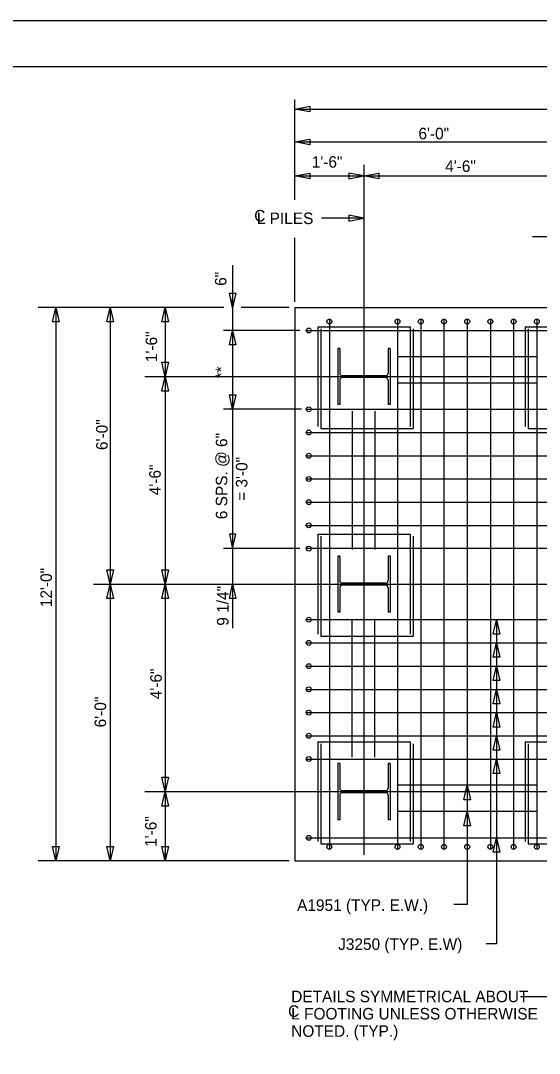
# Model space of a CAD drawing. Extents: x 1970675.2 to 1970711.3, y 796145.2 to 796167.2.
# Drawn here: x 1970688.23 to 1970693.86, y 796156.05 to 796167.25 of the extents above; entities that cross this region are included whole.
import ezdxf

# ---------------------------------------------------------------- set-up
doc = ezdxf.new("R2010")
doc.units = 0
for name, color, linetype in [('BR_AUTO DIMENSION', 7, 'Continuous'), ('BR_BORDER LINES', 7, 'Continuous'), ('BR_CENTER LINES', 7, 'Continuous'), ('BR_CONCRETE', 7, 'Continuous'), ('BR_REBAR', 7, 'Continuous'), ('BR_STRUCTURAL STEEL', 7, 'Continuous'), ('BR_TEXT', 7, 'Continuous'), ('Level 31', 7, 'Continuous')]:
    doc.layers.add(name, color=color, linetype=linetype)

msp = doc.modelspace()

# ---------------------------------------------------------------- linework, layer by layer
at = {"layer": 'BR_AUTO DIMENSION'}
for p, q in [((1970691.208, 796165.302), (1970691.208, 796166.393)), ((1970691.208, 796166.288), (1970697.208, 796166.288)), ((1970691.208, 796165.931), (1970694.208, 796165.931)), ((1970691.208, 796165.563), (1970691.958, 796165.563)), ((1970691.958, 796165.563), (1970694.208, 796165.563)), ((1970691.958, 796165.105), (1970691.497, 796165.105)), ((1970691.208, 796164.197), (1970691.208, 796164.89)), ((1970694.208, 796164.904), (1970693.787, 796164.904)), ((1970690.534, 796164.597), (1970690.534, 796160.661)), ((1970690.534, 796164.137), (1970690.534, 796164.24)), ((1970690.439, 796164.137), (1970688.423, 796164.137)), ((1970688.615, 796164.137), (1970688.615, 796158.137)), ((1970689.204, 796164.137), (1970689.204, 796161.137)), ((1970689.802, 796164.137), (1970689.802, 796163.387)), ((1970691.148, 796164.137), (1970690.628, 796164.137)), ((1970691.264, 796163.887), (1970690.435, 796163.887)), ((1970689.802, 796163.387), (1970689.802, 796161.137)), ((1970691.282, 796163.033), (1970690.435, 796163.033)), ((1970691.261, 796161.522), (1970690.435, 796161.522)), ((1970689.204, 796161.137), (1970689.204, 796158.137)), ((1970689.802, 796161.137), (1970689.802, 796158.137)), ((1970693.397, 796160.751), (1970693.397, 796157.238)), ((1970693.079, 796158.956), (1970693.079, 796157.664)), ((1970689.802, 796158.762), (1970689.802, 796158.663)), ((1970689.802, 796158.137), (1970689.802, 796158.227)), ((1970691.148, 796158.137), (1970688.423, 796158.137)), ((1970693.079, 796157.664), (1970692.934, 796157.664)), ((1970693.397, 796157.238), (1970693.283, 796157.238)), ((1970694.208, 796156.663), (1970693.656, 796156.663))]:
    msp.add_line(p, q, dxfattribs=at)
for points in [[(1970691.37, 796166.257), (1970691.208, 796166.288), (1970691.37, 796166.319)], [(1970691.37, 796165.9), (1970691.208, 796165.931), (1970691.37, 796165.962)], [(1970691.37, 796165.532), (1970691.208, 796165.563), (1970691.37, 796165.594)], [(1970691.795, 796165.532), (1970691.958, 796165.563), (1970691.795, 796165.594)], [(1970692.12, 796165.532), (1970691.958, 796165.563), (1970692.12, 796165.594)], [(1970691.795, 796165.074), (1970691.958, 796165.105), (1970691.795, 796165.136)], [(1970690.57, 796164.293), (1970690.534, 796164.137), (1970690.498, 796164.293)], [(1970688.579, 796163.981), (1970688.615, 796164.137), (1970688.651, 796163.981)], [(1970689.168, 796163.981), (1970689.204, 796164.137), (1970689.24, 796163.981)], [(1970689.766, 796163.981), (1970689.802, 796164.137), (1970689.838, 796163.981)], [(1970690.498, 796163.731), (1970690.534, 796163.887), (1970690.57, 796163.731)], [(1970689.837, 796163.545), (1970689.801, 796163.389), (1970689.765, 796163.545)], [(1970689.766, 796163.231), (1970689.802, 796163.387), (1970689.838, 796163.231)], [(1970690.57, 796163.189), (1970690.534, 796163.033), (1970690.498, 796163.189)], [(1970690.498, 796161.678), (1970690.534, 796161.522), (1970690.57, 796161.678)], [(1970689.24, 796161.293), (1970689.204, 796161.137), (1970689.168, 796161.293)], [(1970689.838, 796161.293), (1970689.802, 796161.137), (1970689.766, 796161.293)], [(1970689.168, 796160.981), (1970689.204, 796161.137), (1970689.24, 796160.981)], [(1970689.766, 796160.981), (1970689.802, 796161.137), (1970689.838, 796160.981)], [(1970690.498, 796160.981), (1970690.534, 796161.137), (1970690.57, 796160.981)], [(1970693.361, 796160.595), (1970693.397, 796160.751), (1970693.433, 796160.595)], [(1970693.361, 796160.344), (1970693.397, 796160.5), (1970693.433, 796160.344)], [(1970693.361, 796160.092), (1970693.397, 796160.248), (1970693.433, 796160.092)], [(1970693.361, 796159.84), (1970693.397, 796159.996), (1970693.433, 796159.84)], [(1970693.361, 796159.588), (1970693.397, 796159.744), (1970693.433, 796159.588)], [(1970693.361, 796159.337), (1970693.397, 796159.493), (1970693.433, 796159.337)], [(1970693.361, 796159.085), (1970693.397, 796159.241), (1970693.433, 796159.085)], [(1970689.838, 796159.043), (1970689.802, 796158.887), (1970689.766, 796159.043)], [(1970689.766, 796158.731), (1970689.802, 796158.887), (1970689.838, 796158.731)], [(1970693.043, 796158.8), (1970693.079, 796158.956), (1970693.115, 796158.8)], [(1970693.043, 796158.515), (1970693.079, 796158.671), (1970693.115, 796158.515)], [(1970693.361, 796158.231), (1970693.397, 796158.387), (1970693.433, 796158.231)], [(1970688.651, 796158.293), (1970688.615, 796158.137), (1970688.579, 796158.293)], [(1970689.24, 796158.293), (1970689.204, 796158.137), (1970689.168, 796158.293)], [(1970689.838, 796158.293), (1970689.802, 796158.137), (1970689.766, 796158.293)]]:
    msp.add_lwpolyline(points, close=True, dxfattribs=at)
at = {"layer": 'BR_BORDER LINES'}
msp.add_line((1970710.736, 796166.746), (1970677.07, 796166.746), dxfattribs=at)
at = {"layer": 'BR_CENTER LINES'}
for p, q in [((1970691.958, 796165.684), (1970691.958, 796158.201)), ((1970689.58, 796163.387), (1970698.526, 796163.387)), ((1970689.025, 796161.137), (1970699.298, 796161.137)), ((1970689.58, 796158.887), (1970698.435, 796158.887))]:
    msp.add_line(p, q, dxfattribs=at)
at = {"layer": 'BR_CONCRETE'}
for p, q in [((1970691.208, 796164.137), (1970697.208, 796164.137)), ((1970691.208, 796164.137), (1970691.208, 796158.137)), ((1970691.208, 796158.137), (1970697.208, 796158.137))]:
    msp.add_line(p, q, dxfattribs=at)
at = {"layer": 'BR_REBAR'}
for p, q in [((1970691.458, 796163.928), (1970692.458, 796163.928)), ((1970691.458, 796163.928), (1970691.458, 796162.845)), ((1970691.49, 796163.906), (1970691.49, 796162.823)), ((1970691.583, 796164.012), (1970691.583, 796158.262)), ((1970692.322, 796164.012), (1970692.322, 796158.262)), ((1970692.458, 796163.928), (1970692.458, 796162.845)), ((1970692.49, 796163.906), (1970692.49, 796162.823)), ((1970692.574, 796164.012), (1970692.574, 796158.262)), ((1970692.826, 796164.012), (1970692.826, 796158.262)), ((1970693.078, 796164.012), (1970693.078, 796158.262)), ((1970693.329, 796164.012), (1970693.329, 796158.262)), ((1970693.581, 796164.012), (1970693.581, 796158.262)), ((1970693.708, 796163.928), (1970694.708, 796163.928)), ((1970693.708, 796163.928), (1970693.708, 796162.845)), ((1970693.74, 796163.906), (1970693.74, 796162.823)), ((1970693.833, 796164.012), (1970693.833, 796158.262)), ((1970693.833, 796164.012), (1970693.833, 796158.262)), ((1970691.333, 796163.887), (1970697.083, 796163.887)), ((1970693.833, 796163.602), (1970692.333, 796163.602)), ((1970693.833, 796163.317), (1970692.333, 796163.317)), ((1970691.333, 796163.033), (1970697.083, 796163.033)), ((1970691.829, 796163.012), (1970691.829, 796161.512)), ((1970692.076, 796163.012), (1970692.076, 796161.512)), ((1970691.49, 796162.823), (1970692.49, 796162.823)), ((1970693.74, 796162.823), (1970694.74, 796162.823)), ((1970691.333, 796162.781), (1970697.083, 796162.781)), ((1970691.333, 796162.529), (1970697.083, 796162.529)), ((1970691.333, 796162.277), (1970697.083, 796162.277)), ((1970691.333, 796162.026), (1970697.083, 796162.026)), ((1970691.333, 796161.774), (1970697.083, 796161.774)), ((1970691.458, 796161.678), (1970692.458, 796161.678)), ((1970691.458, 796161.678), (1970691.458, 796160.595)), ((1970692.458, 796161.678), (1970692.458, 796160.595)), ((1970691.49, 796161.656), (1970691.49, 796160.573)), ((1970692.49, 796161.656), (1970692.49, 796160.573)), ((1970697.083, 796161.522), (1970691.333, 796161.522)), ((1970692.416, 796161.137), (1970696, 796161.137)), ((1970697.083, 796160.751), (1970691.333, 796160.751)), ((1970691.829, 796159.262), (1970691.829, 796160.762)), ((1970692.076, 796159.262), (1970692.076, 796160.762)), ((1970691.49, 796160.573), (1970692.49, 796160.573)), ((1970691.333, 796160.5), (1970697.083, 796160.5)), ((1970691.333, 796160.248), (1970697.083, 796160.248)), ((1970691.333, 796159.996), (1970697.083, 796159.996)), ((1970691.333, 796159.744), (1970697.083, 796159.744)), ((1970691.333, 796159.493), (1970697.083, 796159.493)), ((1970691.458, 796159.428), (1970692.458, 796159.428)), ((1970691.458, 796159.428), (1970691.458, 796158.345)), ((1970692.458, 796159.428), (1970692.458, 796158.345)), ((1970693.708, 796159.428), (1970694.708, 796159.428)), ((1970693.708, 796159.428), (1970693.708, 796158.345)), ((1970691.49, 796159.406), (1970691.49, 796158.323)), ((1970692.49, 796159.406), (1970692.49, 796158.323)), ((1970693.74, 796159.406), (1970693.74, 796158.323)), ((1970691.333, 796159.241), (1970697.083, 796159.241)), ((1970693.833, 796158.956), (1970692.333, 796158.956)), ((1970693.833, 796158.671), (1970692.333, 796158.671)), ((1970691.333, 796158.387), (1970697.083, 796158.387)), ((1970691.49, 796158.323), (1970692.49, 796158.323)), ((1970693.74, 796158.323), (1970694.74, 796158.323))]:
    msp.add_line(p, q, dxfattribs=at)
for centre in [(1970691.359, 796163.887), (1970691.583, 796163.985), (1970692.322, 796163.985), (1970692.574, 796163.985), (1970692.826, 796163.985), (1970693.078, 796163.985), (1970693.329, 796163.985), (1970693.581, 796163.985), (1970693.833, 796163.985), (1970693.833, 796163.985), (1970691.359, 796163.033), (1970691.359, 796162.781), (1970691.359, 796162.529), (1970691.359, 796162.277), (1970691.359, 796162.026), (1970691.359, 796161.774), (1970691.359, 796161.522), (1970691.359, 796160.751), (1970691.359, 796160.5), (1970691.359, 796160.248), (1970691.359, 796159.996), (1970691.359, 796159.744), (1970691.359, 796159.493), (1970691.359, 796159.241), (1970691.359, 796158.387), (1970691.583, 796158.288), (1970692.322, 796158.288), (1970692.574, 796158.288), (1970692.826, 796158.288), (1970693.078, 796158.288), (1970693.329, 796158.288), (1970693.581, 796158.288), (1970693.833, 796158.288), (1970693.833, 796158.288)]:
    msp.add_circle(centre, 0.0265, dxfattribs=at)
at = {"layer": 'BR_STRUCTURAL STEEL'}
for p, q in [((1970691.675, 796163.691), (1970691.675, 796163.083)), ((1970691.695, 796163.691), (1970691.675, 796163.691)), ((1970691.695, 796163.691), (1970691.695, 796163.425)), ((1970692.22, 796163.691), (1970692.22, 796163.425)), ((1970692.241, 796163.691), (1970692.22, 796163.691)), ((1970692.241, 796163.691), (1970692.241, 796163.083)), ((1970691.695, 796163.348), (1970691.695, 796163.083)), ((1970692.192, 796163.397), (1970691.723, 796163.397)), ((1970692.192, 796163.376), (1970691.723, 796163.376)), ((1970692.22, 796163.348), (1970692.22, 796163.083)), ((1970691.695, 796163.083), (1970691.675, 796163.083)), ((1970692.241, 796163.083), (1970692.22, 796163.083)), ((1970691.675, 796161.441), (1970691.675, 796160.833)), ((1970691.695, 796161.441), (1970691.675, 796161.441)), ((1970691.695, 796161.441), (1970691.695, 796161.175)), ((1970692.22, 796161.441), (1970692.22, 796161.175)), ((1970692.241, 796161.441), (1970692.22, 796161.441)), ((1970692.241, 796161.441), (1970692.241, 796160.833)), ((1970692.192, 796161.147), (1970691.723, 796161.147)), ((1970692.192, 796161.126), (1970691.723, 796161.126)), ((1970691.695, 796161.098), (1970691.695, 796160.833)), ((1970692.22, 796161.098), (1970692.22, 796160.833)), ((1970691.695, 796160.833), (1970691.675, 796160.833)), ((1970692.241, 796160.833), (1970692.22, 796160.833)), ((1970691.675, 796159.191), (1970691.675, 796158.583)), ((1970691.695, 796159.191), (1970691.675, 796159.191)), ((1970691.695, 796159.191), (1970691.695, 796158.925)), ((1970692.22, 796159.191), (1970692.22, 796158.925)), ((1970692.241, 796159.191), (1970692.22, 796159.191)), ((1970692.241, 796159.191), (1970692.241, 796158.583)), ((1970692.192, 796158.897), (1970691.723, 796158.897)), ((1970692.192, 796158.876), (1970691.723, 796158.876)), ((1970691.695, 796158.848), (1970691.695, 796158.583)), ((1970692.22, 796158.848), (1970692.22, 796158.583)), ((1970691.695, 796158.583), (1970691.675, 796158.583)), ((1970692.241, 796158.583), (1970692.22, 796158.583))]:
    msp.add_line(p, q, dxfattribs=at)
for centre, start, end in [((1970691.723, 796163.425), 180, 270), ((1970691.723, 796163.348), 90, 180), ((1970692.192, 796163.425), 270, 360), ((1970692.192, 796163.348), 360, 90), ((1970691.723, 796161.175), 180, 270), ((1970691.723, 796161.098), 90, 180), ((1970692.192, 796161.175), 270, 360), ((1970692.192, 796161.098), 360, 90), ((1970691.723, 796158.925), 180, 270), ((1970691.723, 796158.848), 90, 180), ((1970692.192, 796158.925), 270, 360), ((1970692.192, 796158.848), 360, 90)]:
    msp.add_arc(centre, 0.0281, start, end, dxfattribs=at)
at = {"layer": 'Level 31'}
msp.add_lwpolyline([(1970675.236, 796145.246), (1970711.236, 796145.246), (1970711.236, 796167.246), (1970675.236, 796167.246)], close=True, dxfattribs=at)

# ---------------------------------------------------------------- texts
at = {"layer": 'BR_AUTO DIMENSION'}
for s, p in [('6\'-0"', (1970692.549, 796165.96)), ('C', (1970690.768, 796165.069)), ('C', (1970691.135, 796156.445))]:
    msp.add_text(s, height=0.125, dxfattribs=at).set_placement(p)
at = {"layer": 'BR_TEXT'}
for s, p in [('1\'-6"', (1970691.392, 796165.652)), ('4\'-6"', (1970692.839, 796165.606)), ('L PILES', (1970690.796, 796165.041)), ('A1951 (TYP. E.W.)', (1970691.233, 796157.594)), ('J3250 (TYP. E.W)', (1970691.678, 796157.171)), ('DETAILS SYMMETRICAL ABOUT ', (1970691.169, 796156.604)), ('L FOOTING UNLESS OTHERWISE', (1970691.169, 796156.417)), ('NOTED. (TYP.)', (1970691.169, 796156.229))]:
    msp.add_text(s, height=0.125, dxfattribs=at).set_placement(p)
for s, p in [('6"', (1970690.467, 796164.371)), ('1\'-6"', (1970689.715, 796163.544)), ('**', (1970690.474, 796163.368)), ('6\'-0"', (1970689.178, 796162.591)), ('6 SPS. @ 6"', (1970690.476, 796161.841)), ('= 3\'-0"', (1970690.694, 796162.04)), ('4\'-6"', (1970689.754, 796162.101)), ('12\'-0"', (1970688.574, 796160.887)), ('9 1/4"', (1970690.489, 796160.686)), ('4\'-6"', (1970689.765, 796159.889)), ('6\'-0"', (1970689.161, 796159.584)), ('1\'-6"', (1970689.709, 796158.288))]:
    msp.add_text(s, height=0.125, rotation=90, dxfattribs=at).set_placement(p)

doc.saveas('drawing.dxf')
